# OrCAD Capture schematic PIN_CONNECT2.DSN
size A
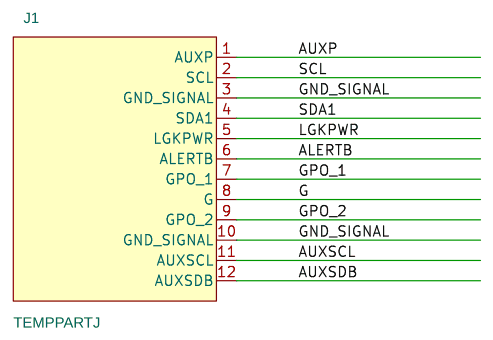
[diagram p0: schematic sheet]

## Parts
J1  TEMPPARTJ

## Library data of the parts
J1 = TEMPPARTJ

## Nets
GND_SIGNAL: J1.3(GND_SIGNAL) J1.10(GND_SIGNAL)
ALERTB: J1.6(ALERTB)
AUXP: J1.1(AUXP)
AUXSCL: J1.11(AUXSCL)
AUXSDB: J1.12(AUXSDB)
G: J1.8(G)
GPO_1: J1.7(GPO_1)
GPO_2: J1.9(GPO_2)
LGKPWR: J1.5(LGKPWR)
SCL: J1.2(SCL)
SDA1: J1.4(SDA1)
